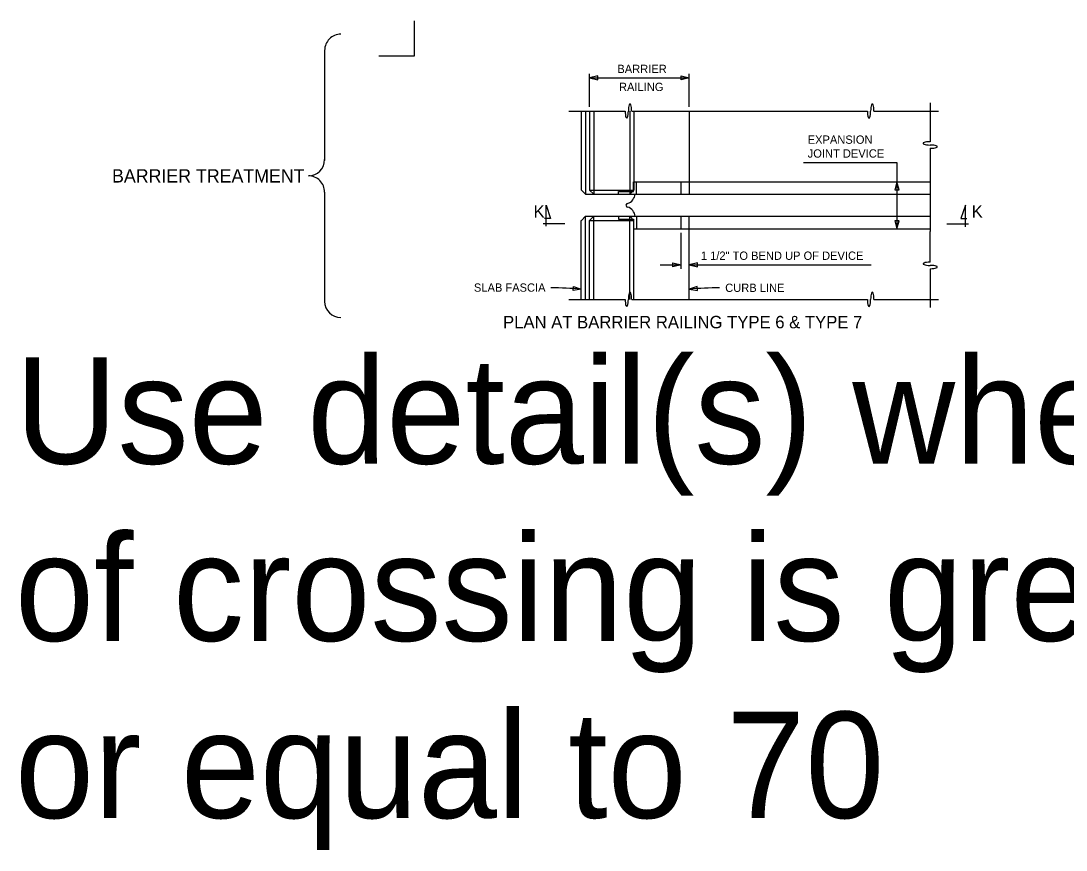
# Model space of a CAD drawing. Extents: x 19590 to 20151, y 19944 to 20103.
# Drawn here: x 19590.5 to 19649.2, y 19964.8 to 20011.4 of the extents above; entities that cross this region are included whole.
import ezdxf

# ---------------------------------------------------------------- set-up
doc = ezdxf.new("R2010")
doc.units = 0
for name, color, linetype in [('DETAIL_PR', 7, 'Continuous'), ('DETAIL_TEXT_DIMEN_PR', 7, 'Continuous'), ('Level 1', 7, 'Continuous')]:
    doc.layers.add(name, color=color, linetype=linetype)

msp = doc.modelspace()

# ---------------------------------------------------------------- linework, layer by layer
at = {"layer": 'DETAIL_PR'}
for p, q in [((19612.577, 20011.351), (19612.577, 20009.361)), ((19612.577, 20009.361), (19610.586, 20009.361)), ((19641.56, 20006.749), (19641.56, 20004.561)), ((19621.266, 20006.283), (19624.426, 20006.283)), ((19621.965, 20006.283), (19621.965, 20001.851)), ((19622.199, 20006.283), (19622.199, 20001.618)), ((19622.432, 20006.283), (19622.432, 20001.851)), ((19622.665, 20006.283), (19622.665, 20001.618)), ((19624.687, 20006.283), (19624.687, 20001.618)), ((19624.793, 20006.283), (19638.033, 20006.283)), ((19624.92, 20006.283), (19624.92, 20001.851)), ((19628.03, 20006.283), (19628.03, 20001.618)), ((19638.4, 20006.283), (19642.026, 20006.283)), ((19641.56, 20004.194), (19641.56, 19999.518)), ((19624.901, 20001.773), (19624.901, 20002.317)), ((19624.901, 20002.317), (19628.03, 20002.317)), ((19625.056, 20001.618), (19625.056, 20002.317)), ((19627.564, 20001.618), (19627.564, 20002.317)), ((19628.03, 20002.317), (19641.56, 20002.317)), ((19622.199, 20001.618), (19621.966, 20001.851)), ((19622.199, 20001.618), (19624.045, 20001.618)), ((19622.432, 20001.851), (19624.92, 20001.851)), ((19622.432, 20001.851), (19622.665, 20001.618)), ((19624.045, 20001.773), (19624.901, 20001.773)), ((19624.046, 20001.618), (19624.046, 20001.773)), ((19624.046, 20001.618), (19641.56, 20001.618)), ((19624.92, 20001.851), (19624.687, 20001.618)), ((19622.199, 20000.374), (19621.966, 20000.14)), ((19622.199, 20000.374), (19624.045, 20000.374)), ((19622.199, 19995.708), (19622.199, 20000.374)), ((19622.432, 20000.14), (19622.665, 20000.374)), ((19622.665, 19995.708), (19622.665, 20000.374)), ((19624.045, 20000.218), (19624.901, 20000.218)), ((19624.046, 20000.374), (19624.046, 20000.218)), ((19624.046, 20000.374), (19641.56, 20000.374)), ((19624.687, 19995.708), (19624.687, 20000.374)), ((19624.92, 20000.14), (19624.687, 20000.373)), ((19624.901, 20000.218), (19624.901, 19999.674)), ((19625.056, 20000.374), (19625.056, 19999.674)), ((19627.564, 19999.674), (19627.564, 20000.374)), ((19628.03, 19995.708), (19628.03, 20000.374)), ((19621.965, 19995.708), (19621.965, 20000.14)), ((19622.432, 19995.708), (19622.432, 20000.14)), ((19622.432, 20000.14), (19624.92, 20000.14)), ((19624.901, 19999.674), (19628.03, 19999.674)), ((19624.92, 19995.708), (19624.92, 20000.14)), ((19628.03, 19999.674), (19641.56, 19999.674)), ((19641.56, 19997.797), (19641.56, 19999.518)), ((19641.56, 19997.43), (19641.56, 19995.242)), ((19621.266, 19995.708), (19624.426, 19995.708)), ((19624.793, 19995.708), (19638.033, 19995.708)), ((19638.4, 19995.708), (19642.026, 19995.708))]:
    msp.add_line(p, q, dxfattribs=at)
for centre, radius, start, end in [((19624.374, 20001.683), 0.618, 288.13646, 353.93158), ((19624.574, 20000.996), 0.101, 94.4387, 265.56132), ((19624.374, 20000.308), 0.618, 6.06842, 71.86353)]:
    msp.add_arc(centre, radius, start, end, dxfattribs=at)
for centre, major_axis, ratio, start_param, end_param in [((19624.701, 20006.283), (0, -0.398), 0.230204, 1.570796, 4.712389), ((19638.308, 20006.283), (0, -0.398), 0.230204, 1.570796, 4.712389), ((19624.517, 20006.283), (0, -0.398), 0.230206, 4.712389, 7.853982), ((19638.125, 20006.283), (0, -0.398), 0.230206, 4.712389, 7.853982), ((19641.56, 20004.47), (0.398, 0), 0.230204, 1.570796, 4.712389), ((19641.56, 20004.286), (0.398, 0), 0.230206, 4.712389, 7.853982), ((19641.56, 19997.705), (0.398, 0), 0.230204, 1.570796, 4.712389), ((19641.56, 19997.522), (0.398, 0), 0.230206, 4.712389, 7.853982), ((19624.701, 19995.708), (0, -0.398), 0.230204, 1.570796, 4.712389), ((19638.308, 19995.708), (0, -0.398), 0.230204, 1.570796, 4.712389), ((19624.517, 19995.708), (0, -0.398), 0.230206, 4.712389, 7.853982), ((19638.125, 19995.708), (0, -0.398), 0.230206, 4.712389, 7.853982)]:
    msp.add_ellipse(centre, major_axis=major_axis, ratio=ratio, start_param=start_param, end_param=end_param, dxfattribs=at)
at = {"layer": 'DETAIL_TEXT_DIMEN_PR'}
for p, q in [((19607.547, 20009.698), (19607.547, 20003.513)), ((19622.432, 20006.516), (19622.432, 20008.382)), ((19628.03, 20006.516), (19628.03, 20008.382)), ((19622.884, 20008.266), (19622.432, 20008.149)), ((19622.432, 20008.149), (19628.03, 20008.149)), ((19622.432, 20008.149), (19622.884, 20008.032)), ((19622.884, 20008.032), (19622.884, 20008.266)), ((19627.579, 20008.266), (19628.03, 20008.149)), ((19627.579, 20008.032), (19627.579, 20008.266)), ((19628.03, 20008.149), (19627.579, 20008.032)), ((19634.436, 20003.406), (19639.694, 20003.406)), ((19639.694, 20003.406), (19639.694, 19999.674)), ((19607.547, 20001.737), (19607.547, 19995.595)), ((19619.984, 19999.814), (19619.983, 20000.996)), ((19619.983, 20000.996), (19620.238, 20000.253)), ((19643.542, 20000.996), (19643.287, 20000.253)), ((19643.542, 19999.787), (19643.542, 20000.996)), ((19620.238, 20000.253), (19619.905, 20000.253)), ((19643.287, 20000.253), (19643.621, 20000.253)), ((19621.032, 19999.946), (19619.816, 19999.946)), ((19642.493, 19999.946), (19643.719, 19999.946)), ((19627.564, 19997.419), (19627.564, 19999.44)), ((19626.397, 19997.652), (19627.564, 19997.652)), ((19628.03, 19997.652), (19638.242, 19997.652))]:
    msp.add_line(p, q, dxfattribs=at)
for centre, radius, start, end in [((19608.457, 20009.698), 0.91, 89.96627, 180.03372), ((19606.637, 20003.557), 0.911, 269.96631, 359.96626), ((19606.637, 20001.736), 0.91, 359.96627, 90.03372), ((19619.518, 19956.873), 39.492, 86.44645, 88.92222), ((19630.478, 19956.873), 39.492, 91.07778, 93.55355), ((19608.457, 19995.595), 0.91, 180.03373, 270.03369)]:
    msp.add_arc(centre, radius, start, end, dxfattribs=at)
at = {"layer": 'Level 1'}
for p, q in [((19639.694, 20002.317), (19639.577, 20001.866)), ((19639.811, 20001.866), (19639.694, 20002.317)), ((19639.577, 20001.866), (19639.811, 20001.866)), ((19639.81, 20000.125), (19639.577, 20000.125)), ((19639.577, 20000.125), (19639.694, 19999.674)), ((19639.694, 19999.674), (19639.81, 20000.125)), ((19627.112, 19997.535), (19627.112, 19997.769)), ((19627.112, 19997.769), (19627.564, 19997.652)), ((19627.564, 19997.652), (19627.112, 19997.535)), ((19628.482, 19997.769), (19628.03, 19997.652)), ((19628.03, 19997.652), (19628.482, 19997.535)), ((19628.482, 19997.535), (19628.482, 19997.769)), ((19621.508, 19996.198), (19621.521, 19996.431)), ((19621.965, 19996.289), (19621.508, 19996.198)), ((19621.521, 19996.431), (19621.965, 19996.289)), ((19628.475, 19996.431), (19628.03, 19996.289)), ((19628.03, 19996.289), (19628.488, 19996.198)), ((19628.488, 19996.198), (19628.475, 19996.431))]:
    msp.add_line(p, q, dxfattribs=at)

# ---------------------------------------------------------------- texts
at = {"layer": 'DETAIL_TEXT_DIMEN_PR'}
for s, height, p in [('BARRIER', 0.4665, (19623.989, 20008.422)), ('RAILING', 0.4665, (19624.082, 20007.411)), ('EXPANSION ', 0.4665, (19634.68, 20004.448)), ('JOINT DEVICE', 0.46653, (19634.68, 20003.671)), ('K', 0.7, (19619.283, 20000.296)), ('K', 0.7, (19643.892, 20000.296)), ('1 1/2" TO BEND UP OF DEVICE', 0.46653, (19628.68, 19997.928)), ('SLAB FASCIA', 0.46653, (19615.933, 19996.137)), ('CURB LINE', 0.4665, (19630.047, 19996.125)), ('PLAN AT BARRIER RAILING TYPE 6 & TYPE 7', 0.69989, (19617.568, 19994.081)), ('Use detail(s) when angle(s) ', 5.97143, (19590.151, 19986.475)), ('of crossing is greater than ', 5.97143, (19590.151, 19976.523)), ('or equal to 70', 5.97143, (19590.151, 19966.571))]:
    msp.add_text(s, height=height, dxfattribs=at).set_placement(p)
msp.add_text('BARRIER TREATMENT', height=0.74643, rotation=360, dxfattribs=at).set_placement((19595.606, 20002.273))

doc.saveas('drawing.dxf')
